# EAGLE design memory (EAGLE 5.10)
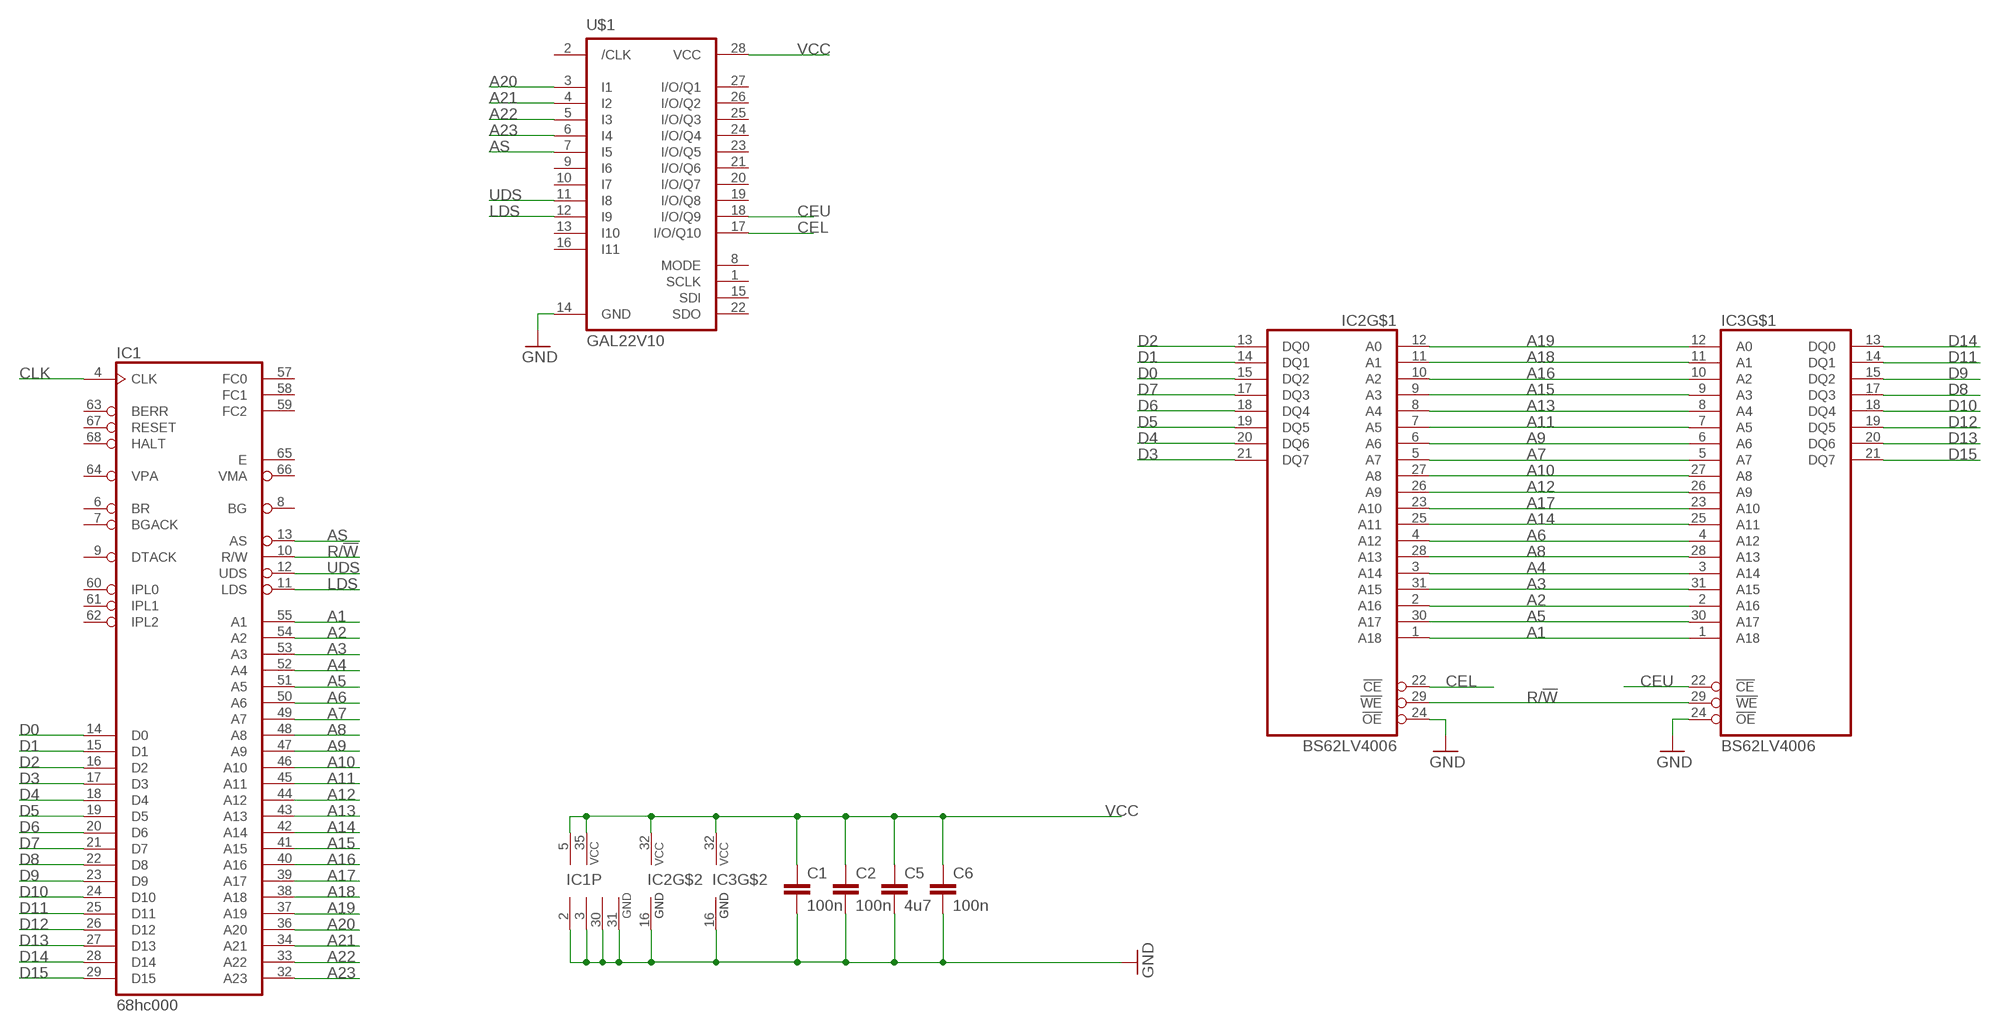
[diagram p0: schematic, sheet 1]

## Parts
C1  100n  C-EUC1206K  [C1206K]
C2  100n  C-EUC1206K  [C1206K]
C5  4u7  C-EUC1206K  [C1206K]
C6  100n  C-EUC1206K  [C1206K]
IC1  68hc000  MC68000FNPLCC-S_MIRROR  [PLCC68-S]
IC2  BS62LV4006  [DIL32]
IC3  BS62LV4006  [DIL32]
U$1  GAL22V10  [PLCC28S]

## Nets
A1: IC1.55(A1) IC2.1(A18) IC3.1(A18)
A2: IC1.54(A2) IC2.2(A16) IC3.2(A16)
A3: IC1.53(A3) IC2.31(A15) IC3.31(A15)
A4: IC1.52(A4) IC2.3(A14) IC3.3(A14)
A5: IC1.51(A5) IC2.30(A17) IC3.30(A17)
A6: IC1.50(A6) IC2.4(A12) IC3.4(A12)
A7: IC1.49(A7) IC2.5(A7) IC3.5(A7)
A8: IC1.48(A8) IC2.28(A13) IC3.28(A13)
A9: IC1.47(A9) IC2.6(A6) IC3.6(A6)
A10: IC1.46(A10) IC2.27(A8) IC3.27(A8)
A11: IC1.45(A11) IC2.7(A5) IC3.7(A5)
A12: IC1.44(A12) IC2.26(A9) IC3.26(A9)
A13: IC1.43(A13) IC2.8(A4) IC3.8(A4)
A14: IC1.42(A14) IC2.25(A11) IC3.25(A11)
A15: IC1.41(A15) IC2.9(A3) IC3.9(A3)
A16: IC1.40(A16) IC2.10(A2) IC3.10(A2)
A17: IC1.39(A17) IC2.23(A10) IC3.23(A10)
A18: IC1.38(A18) IC2.11(A1) IC3.11(A1)
A19: IC1.37(A19) IC2.12(A0) IC3.12(A0)
A20: IC1.36(A20) U$1.3(I1)
A21: IC1.34(A21) U$1.4(I2)
A22: IC1.33(A22) U$1.5(I3)
A23: IC1.32(A23) U$1.6(I4)
AS: IC1.13(AS) U$1.7(I5)
CEL: IC2.22(!CE) U$1.17(I/O/Q10)
CEU: IC3.22(!CE) U$1.18(I/O/Q9)
CLK: IC1.4(CLK)
D0: IC1.14(D0) IC2.15(DQ2)
D1: IC1.15(D1) IC2.14(DQ1)
D2: IC1.16(D2) IC2.13(DQ0)
D3: IC1.17(D3) IC2.21(DQ7)
D4: IC1.18(D4) IC2.20(DQ6)
D5: IC1.19(D5) IC2.19(DQ5)
D6: IC1.20(D6) IC2.18(DQ4)
D7: IC1.21(D7) IC2.17(DQ3)
D8: IC1.22(D8) IC3.17(DQ3)
D9: IC1.23(D9) IC3.15(DQ2)
D10: IC1.24(D10) IC3.18(DQ4)
D11: IC1.25(D11) IC3.14(DQ1)
D12: IC1.26(D12) IC3.19(DQ5)
D13: IC1.27(D13) IC3.20(DQ6)
D14: IC1.28(D14) IC3.13(DQ0)
D15: IC1.29(D15) IC3.21(DQ7)
GND: C1.2 C2.2 C5.2 C6.2 IC1.2(GND) IC1.3(GND) IC1.30(GND) IC1.31(GND) IC2.16(GND) IC2.24(!OE) IC3.16(GND) IC3.24(!OE) U$1.14(GND)
LDS: IC1.11(LDS) U$1.12(I9)
R/!W: IC1.10(R/W) IC2.29(!WE) IC3.29(!WE)
UDS: IC1.12(UDS) U$1.11(I8)
VCC: C1.1 C2.1 C5.1 C6.1 IC1.5(VCC) IC1.35(VCC) IC2.32(VCC) IC3.32(VCC) U$1.28(VCC)
Unconnected: IC1.6(BR) IC1.7(BGACK) IC1.8(BG) IC1.9(DTACK) IC1.57(FC0) IC1.58(FC1) IC1.59(FC2) IC1.60(IPL0) IC1.61(IPL1) IC1.62(IPL2) IC1.63(BERR) IC1.64(VPA) IC1.65(E) IC1.66(VMA) IC1.67(RESET) IC1.68(HALT) U$1.1(SCLK) U$1.2(/CLK) U$1.8(MODE) U$1.9(I6) U$1.10(I7) U$1.13(I10) U$1.15(SDI) U$1.16(I11) U$1.19(I/O/Q8) U$1.20(I/O/Q7) U$1.21(I/O/Q6) U$1.22(SDO) U$1.23(I/O/Q5) U$1.24(I/O/Q4) U$1.25(I/O/Q3) U$1.26(I/O/Q2) U$1.27(I/O/Q1)

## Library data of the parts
C1 C2 C5 C6 = rcl:C-EU: CAPACITOR, European symbol
IC1 = micro-mc68000_v2:MC68000FN: 68xxx PROCESSOR
IC2 IC3 = Memory_zz:BS62LV4006
U$1 = lattice_gal:GAL22V10

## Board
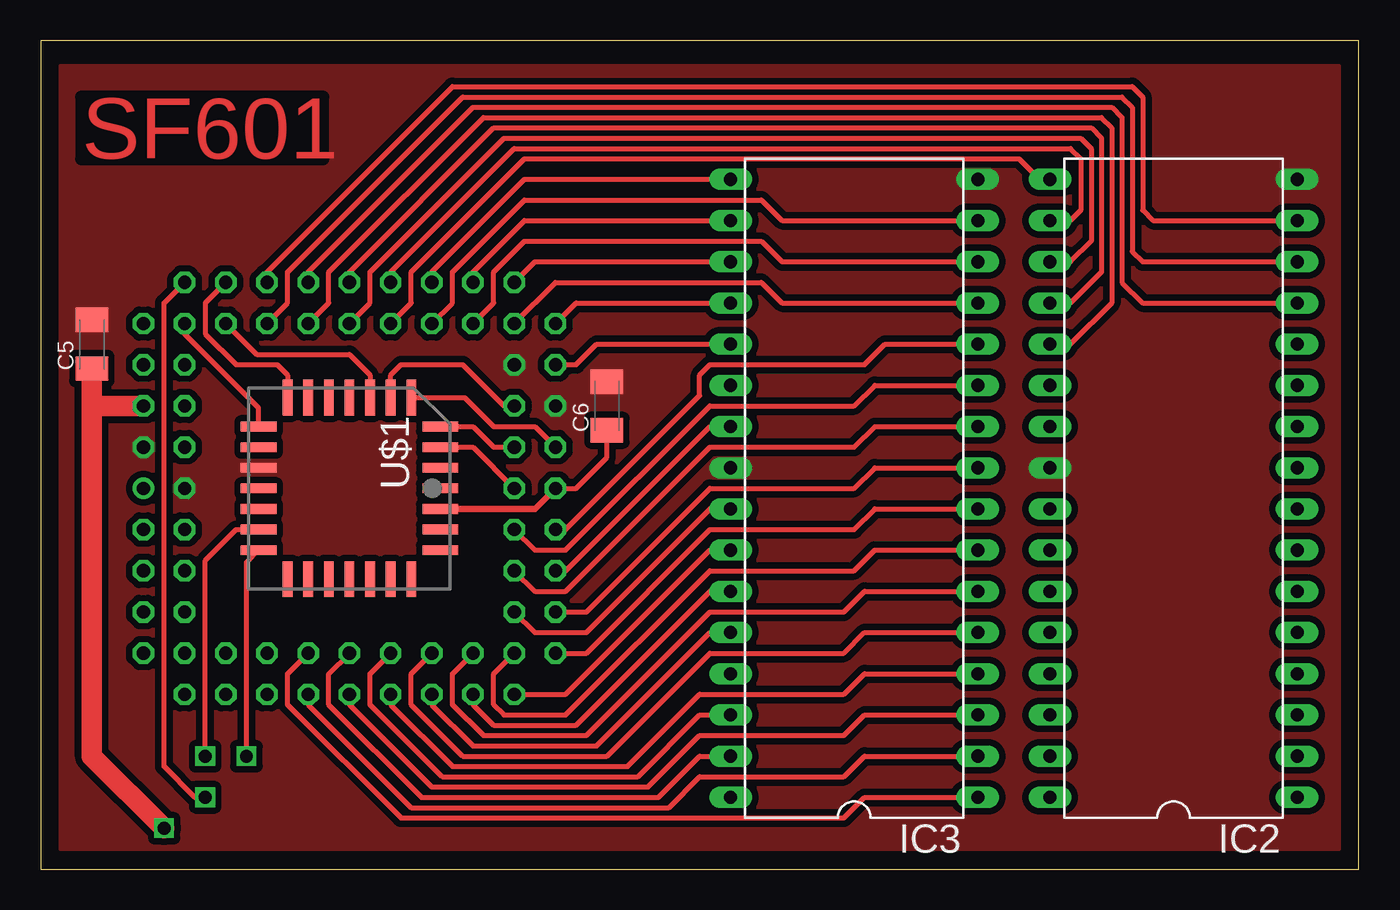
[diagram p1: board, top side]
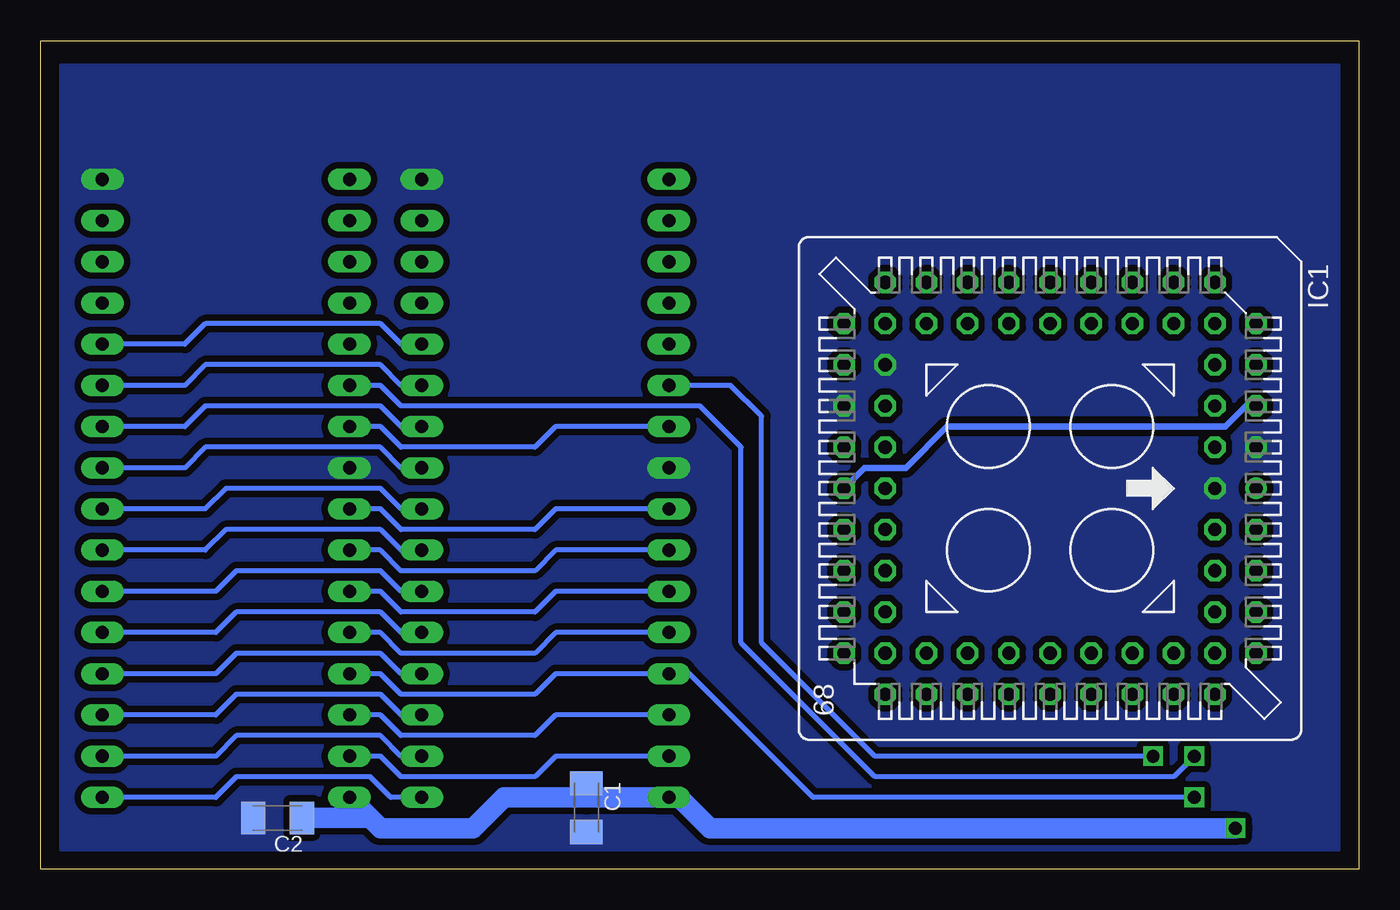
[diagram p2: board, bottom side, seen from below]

Size 81.27 x 51.1 mm. Coordinates in mm from the lower left corner, seen from the top.
Outline: 81.27,0 81.27,51.1 0,51.1 0,0 81.27,0
Copper layers (1*16): Top 0.035mm / dielectric 1.5mm / Bottom 0.035mm
Design rules "default *": minimum track width 10mil, minimum drill 24mil, track to track 12mil, track to pad 12mil, pad to pad 12mil, via to via 12mil, smd to smd 12mil, copper to edge 40mil, drill to drill 8mil, minimum pad ring 10mil, minimum via ring 8mil, stop-mask expansion 4mil, vias tented up to drill 0mil, thermal gap 10mil

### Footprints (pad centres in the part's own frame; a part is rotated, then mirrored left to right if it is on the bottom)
C1206K = smd 1.5 x 2: 1 -1.5,0; 2 1.5,0
PLCC68-S = drill 0.813 round: 1 0,12.7 | drill 0.813 octagon: 2 0,10.16; 3 -2.54,12.7; 4 -2.54,10.16; 5 -5.08,12.7; 6 -5.08,10.16; 7 -7.62,12.7; 8 -7.62,10.16; 9 -10.16,12.7; 10 -12.7,10.16; 11 -10.16,10.16; 12 -12.7,7.62; 13 -10.16,7.62; 14 -12.7,5.08; 15 -10.16,5.08; 16 -12.7,2.54; 17 -10.16,2.54; 18 -12.7,0; 19 -10.16,0; 20 -12.7,-2.54; 21 -10.16,-2.54; 22 -12.7,-5.08; 23 -10.16,-5.08; 24 -12.7,-7.62; 25 -10.16,-7.62; 26 -12.7,-10.16; 27 -10.16,-12.7; 28 -10.16,-10.16; 29 -7.62,-12.7; 30 -7.62,-10.16; 31 -5.08,-12.7; 32 -5.08,-10.16; 33 -2.54,-12.7; 34 -2.54,-10.16; 35 0,-12.7; 36 0,-10.16; 37 2.54,-12.7; 38 2.54,-10.16; 39 5.08,-12.7; 40 5.08,-10.16; 41 7.62,-12.7; 42 7.62,-10.16; 43 10.16,-12.7; 44 12.7,-10.16; 45 10.16,-10.16; 46 12.7,-7.62; 47 10.16,-7.62; 48 12.7,-5.08; 49 10.16,-5.08; 50 12.7,-2.54; 51 10.16,-2.54; 52 12.7,0; 53 10.16,0; 54 12.7,2.54; 55 10.16,2.54; 56 12.7,5.08; 57 10.16,5.08; 58 12.7,7.62; 59 10.16,7.62; 60 12.7,10.16; 61 10.16,12.7; 62 10.16,10.16; 63 7.62,12.7; 64 7.62,10.16; 65 5.08,12.7; 66 5.08,10.16; 67 2.54,12.7; 68 2.54,10.16
DIL32 = drill 0.813 long: 1 -19.05,-7.62; 2 -16.51,-7.62; 3 -13.97,-7.62; 4 -11.43,-7.62; 5 -8.89,-7.62; 6 -6.35,-7.62; 7 -3.81,-7.62; 8 -1.27,-7.62; 9 1.27,-7.62; 10 3.81,-7.62; 11 6.35,-7.62; 12 8.89,-7.62; 13 11.43,-7.62; 14 13.97,-7.62; 15 16.51,-7.62; 16 19.05,-7.62; 17 19.05,7.62; 18 16.51,7.62; 19 13.97,7.62; 20 11.43,7.62; 21 8.89,7.62; 22 6.35,7.62; 23 3.81,7.62; 24 1.27,7.62; 25 -1.27,7.62; 26 -3.81,7.62; 27 -6.35,7.62; 28 -8.89,7.62; 29 -11.43,7.62; 30 -13.97,7.62; 31 -16.51,7.62; 32 -19.05,7.62
PLCC28S = smd 0.6 x 2.2: 1 0,5.6; 2 -1.27,5.6; 3 -2.54,5.6; 4 -3.81,5.6; 12 -3.81,-5.6; 13 -2.54,-5.6; 14 -1.27,-5.6; 15 0,-5.6; 16 1.27,-5.6; 17 2.54,-5.6; 18 3.81,-5.6; 26 3.81,5.6; 27 2.54,5.6; 28 1.27,5.6 | smd 2.2 x 0.6: 5 -5.6,3.81; 6 -5.6,2.54; 7 -5.6,1.27; 8 -5.6,0; 9 -5.6,-1.27; 10 -5.6,-2.54; 11 -5.6,-3.81; 19 5.6,-3.81; 20 5.6,-2.54; 21 5.6,-1.27; 22 5.6,0; 23 5.6,1.27; 24 5.6,2.54; 25 5.6,3.81

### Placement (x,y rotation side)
C1  47.62,3.81 270 bottom
C2  66.66,3.17 180 bottom
C5  3.17,32.38 90 top
C6  34.91,28.57 90 top
IC1  19.04,23.5 270 bottom
IC2  69.84,23.5 90 top
IC3  50.16,23.5 90 top
U$1  19.04,23.5 270 top

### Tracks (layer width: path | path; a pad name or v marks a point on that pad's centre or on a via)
A1
  Top 0.305: IC3.1 50.79,4.45 49.52,3.17 22.21,3.17 15.23,10.16 15.23,12.06 IC1.55
  Bottom 0.305: IC3.1 59.68,4.45 60.95,5.71 69.2,5.71 70.47,4.45 IC2.1
A2
  Top 0.305: IC3.2 50.79,6.99 49.52,5.71 40.63,5.71 38.73,3.81 22.85,3.81 16.5,10.16 IC1.54
  Bottom 0.305: IC2.2 70.47,6.99 69.2,8.26 60.32,8.26 59.05,6.99 IC3.2
A3
  Top 0.305: IC3.31 40.63,6.99 38.09,4.45 23.48,4.45 17.77,10.16 17.77,12.06 IC1.53
  Bottom 0.305: IC2.31 60.32,6.99 59.05,5.71 50.79,5.71 49.52,6.99 IC3.31
A4
  Top 0.305: IC3.3 50.79,9.53 49.52,8.26 40.63,8.26 37.46,5.08 24.12,5.08 19.04,10.16 IC1.52
  Bottom 0.305: IC2.3 70.47,9.53 69.2,10.79 60.32,10.79 59.05,9.53 IC3.3
A5
  Top 0.305: IC3.30 40.63,9.53 36.82,5.71 24.75,5.71 20.31,10.16 20.31,12.06 IC1.51
  Bottom 0.305: IC3.30 49.52,9.53 50.79,8.26 59.05,8.26 60.32,9.53 IC2.30
A6
  Top 0.305: IC3.4 50.79,12.06 49.52,10.79 40.63,10.79 36.19,6.35 25.39,6.35 21.58,10.16 IC1.50
  Bottom 0.305: IC2.4 70.47,12.06 69.2,13.34 60.32,13.34 59.05,12.06 IC3.4
A7
  Top 0.305: IC3.5 50.79,14.61 49.52,13.34 41.27,13.34 34.91,6.99 26.02,6.99 22.85,10.16 22.85,12.06 IC1.49
  Bottom 0.305: IC2.5 70.47,14.61 69.2,15.88 60.32,15.88 59.05,14.61 IC3.5
A8
  Top 0.305: IC3.28 41.27,14.61 34.28,7.62 26.66,7.62 24.12,10.16 IC1.48
  Bottom 0.305: IC2.28 60.32,14.61 59.05,13.34 50.79,13.34 49.52,14.61 IC3.28
A9
  Top 0.305: IC1.47 25.39,12.06 25.39,10.16 27.29,8.26 33.65,8.26 41.27,15.88 49.52,15.88 50.79,17.14 IC3.6
  Bottom 0.305: IC2.6 70.47,17.14 69.2,18.41 60.32,18.41 59.05,17.14 IC3.6
A10
  Top 0.305: IC1.46 26.66,10.16 27.93,8.89 33.01,8.89 41.27,17.14 IC3.27
  Bottom 0.305: IC2.27 60.32,17.14 59.05,15.88 50.79,15.88 49.52,17.14 IC3.27
A11
  Top 0.305: IC3.7 51.43,19.68 50.16,18.41 41.27,18.41 32.38,9.53 28.56,9.53 27.93,10.16 27.93,12.06 IC1.45
  Bottom 0.305: IC2.7 71.11,19.68 69.84,20.95 60.32,20.95 59.05,19.68 IC3.7
A12
  Top 0.305: IC1.44 32.38,10.79 41.27,19.68 IC3.26
  Bottom 0.305: IC2.26 60.32,19.68 59.05,18.41 50.79,18.41 49.52,19.68 IC3.26
A13
  Top 0.305: IC1.43 33.65,13.34 41.27,20.95 50.16,20.95 51.43,22.23 IC3.8
  Bottom 0.305: IC2.8 71.11,22.23 69.84,23.5 60.32,23.5 59.05,22.23 IC3.8
A14
  Top 0.305: IC3.25 41.27,22.23 33.65,14.61 30.47,14.61 IC1.42
  Bottom 0.305: IC2.25 60.32,22.23 59.05,20.95 50.79,20.95 49.52,22.23 IC3.25
A15
  Top 0.305: IC3.9 51.43,24.77 50.16,23.5 41.27,23.5 33.65,15.88 IC1.41
  Bottom 0.305: IC2.9 72.38,24.77 71.11,26.04 60.32,26.04 59.05,24.77 IC3.9
A16
  Top 0.305: IC3.10 51.43,27.3 50.16,26.04 41.27,26.04 32.38,17.14 30.47,17.14 IC1.40
  Bottom 0.305: IC2.10 72.38,27.3 71.11,28.57 60.32,28.57 59.05,27.3 IC3.10
A17
  Top 0.305: IC1.39 32.38,18.41 41.27,27.3 IC3.23
  Bottom 0.305: IC2.23 60.32,27.3 59.05,26.04 50.79,26.04 49.52,27.3 IC3.23
A18
  Top 0.305: IC3.11 51.43,29.84 50.16,28.57 41.27,28.57 32.38,19.68 30.47,19.68 IC1.38
  Bottom 0.305: IC2.11 72.38,29.84 71.11,31.11 60.32,31.11 59.05,29.84 IC3.11
A19
  Top 0.305: IC3.12 52.06,32.38 50.79,31.11 41.27,31.11 40.63,30.48 40.63,29.21 32.38,20.95 IC1.37
  Bottom 0.305: IC2.12 72.38,32.38 71.11,33.66 60.32,33.66 59.05,32.38 IC3.12
A20
  Top 0.305: U$1.3 26.66,26.04 IC1.36
A21
  Top 0.305: U$1.4 26.66,27.3 27.93,26.04 IC1.34
A22
  Top 0.305: U$1.5 26.14,29.09 27.93,27.3 30.47,27.3 IC1.33
A23
  Top 0.305: IC1.32 28.56,28.57 26.02,31.11 22.21,31.11 21.58,30.48 U$1.6
AS
  Top 0.305: U$1.7 20.31,30.48 19.04,31.75 13.33,31.75 IC1.13
CEL  (via drill 0.8)
  Top 0.305: v10.15,6.99 10.15,19.05 12.05,20.95 U$1.17
  Bottom 0.305: IC2.22 60.32,29.84 59.05,28.57 40.63,28.57 38.09,26.04 38.09,13.97 29.83,5.71 11.42,5.71 v10.15,6.99
CEU  (via drill 0.8)
  Top 0.305: v12.69,6.99 12.69,18.93 U$1.18
  Bottom 0.305: IC3.22 38.73,29.84 36.82,27.94 36.82,13.97 29.83,6.99 v12.69,6.99
D0
  Top 0.305: IC2.15 68.57,40.01 67.93,40.64 67.93,47.62 67.3,48.26 25.39,48.26 13.96,36.83 IC1.14
D1
  Top 0.305: IC2.14 67.93,37.47 67.3,38.1 67.3,46.99 66.66,47.62 26.02,47.62 15.23,36.83 15.23,34.92 IC1.15
D2
  Top 0.305: IC2.13 67.93,34.92 66.66,36.2 66.66,46.35 66.03,46.99 26.66,46.99 16.5,36.83 IC1.16
D3
  Top 0.305: IC2.21 63.49,32.38 66.03,34.92 66.03,45.72 65.39,46.35 27.29,46.35 17.77,36.83 17.77,34.92 IC1.17
D4
  Top 0.305: IC2.20 63.49,34.92 65.39,36.83 65.39,45.09 64.76,45.72 27.93,45.72 19.04,36.83 IC1.18
D5
  Top 0.305: IC2.19 63.49,37.47 64.76,38.73 64.76,44.45 64.12,45.09 28.56,45.09 20.31,36.83 20.31,34.92 IC1.19
D6
  Top 0.305: IC2.18 63.49,40.01 64.12,40.64 64.12,43.81 63.49,44.45 29.2,44.45 21.58,36.83 IC1.20
D7
  Top 0.305: IC2.17 61.59,42.55 60.32,43.81 29.83,43.81 22.85,36.83 22.85,34.92 IC1.21
D8
  Top 0.305: IC3.17 29.83,42.55 24.12,36.83 IC1.22
D9
  Top 0.305: IC3.15 45.71,40.01 44.44,41.27 29.83,41.27 25.39,36.83 25.39,34.92 IC1.23
D10
  Top 0.305: IC3.18 29.83,40.01 26.66,36.83 IC1.24
D11
  Top 0.305: IC3.14 45.71,37.47 44.44,38.73 29.83,38.73 27.93,36.83 27.93,34.92 IC1.25
D12
  Top 0.305: IC3.19 30.47,37.47 IC1.26
D13
  Top 0.305: IC3.20 33.01,34.92 IC1.27
D14
  Top 0.305: IC3.13 45.71,34.92 44.44,36.2 31.74,36.2 IC1.28
D15
  Top 0.305: IC3.21 34.28,32.38 33.01,31.11 IC1.29
GND
  pour Top (isolate 0.406, no thermals): 80,49.53 80,1.27 1.26,1.27 1.26,49.53
  pour Bottom (isolate 0.406, no thermals): 80,49.53 80,1.27 1.26,1.27 1.26,49.53
LDS
  Top 0.305: U$1.12 13.44,28.46 8.88,33.02 IC1.11
R/!W  (via drill 0.8)
  Top 0.305: v10.15,4.45 9.52,4.45 7.61,6.35 7.61,34.92 IC1.10
  Bottom 0.305: IC2.29 60.32,12.06 59.05,10.79 50.79,10.79 49.52,12.06 IC3.29 41.27,12.06 33.65,4.45 v10.15,4.45
UDS
  Top 0.305: IC1.12 10.15,34.92 10.15,33.02 12.05,31.11 14.6,31.11 15.23,30.48 U$1.11
VCC  (via drill 0.8)
  Top 0.305: IC1.35 33.01,23.5 34.91,25.4 C6.1
  Top 0.406: IC1.35 30.47,22.23 U$1.28
  Top 1.27: v7.61,2.54 3.17,6.99 3.17,28.57 | 3.17,28.57 IC1.5 | 3.17,28.57 C5.1
  Bottom 0.305: 41.9,4.45 IC3.32 | 47.62,4.45 C1.1 | IC1.5 6.98,28.57
  Bottom 0.406: 6.98,28.57 8.25,27.3 25.39,27.3 27.93,24.77 30.47,24.77 IC1.35
  Bottom 1.27: 60.95,3.17 60.32,2.54 54.6,2.54 52.7,4.45 47.62,4.45 IC3.32 | 60.95,3.17 IC2.32 | 41.9,4.45 40,2.54 v7.61,2.54 | 60.95,3.17 C2.1

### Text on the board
Top: SF601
